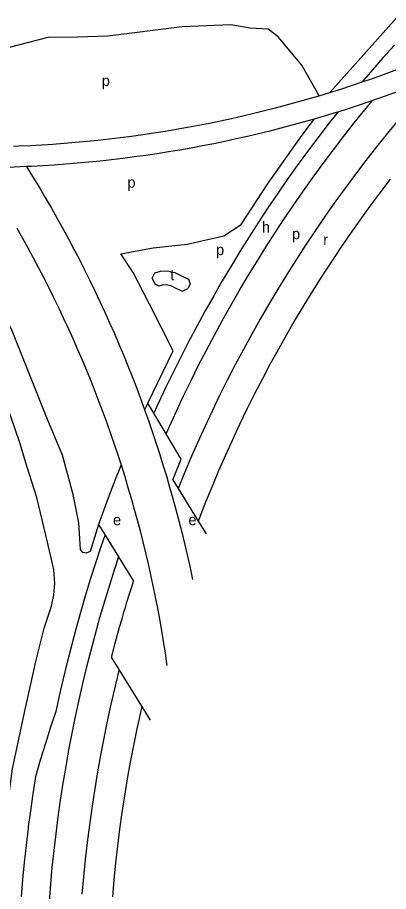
# Model space of a CAD drawing. Extents: x 155209 to 156755, y 386543 to 388502.
# Drawn here: x 156056.9 to 156193.5, y 387840.4 to 388161.9 of the extents above; entities that cross this region are included whole.
import ezdxf

# ---------------------------------------------------------------- set-up
doc = ezdxf.new("R2010")
doc.units = 0
doc.layers.add('BLT_Basislijn', color=7, linetype='Continuous')
doc.layers.add('BLT_Centroide', color=7, linetype='Continuous')

msp = doc.modelspace()

# ---------------------------------------------------------------- linework, layer by layer
at = {"layer": 'BLT_Basislijn'}
for points in [[(156196.55, 388161.95), (156184.36, 388148.27), (156171.92, 388134.38)], [(156167.94, 388133.17), (156161.61, 388144.38), (156152.92, 388154.87), (156149.22, 388157.64), (156142.57, 388158.01), (156135.46, 388159.23), (156117.57, 388158.48), (156090.11, 388155.04), (156078.96, 388154.76), (156068.1, 388154.57), (156049.4, 388149.84)], [(156195.68, 388151.8), (156191.47, 388147.07), (156183.81, 388138.24)], [(156183.81, 388138.24), (156187.58, 388139.54), (156191.43, 388140.9), (156191.64, 388140.98), (156195.55, 388142.41), (156197.63, 388143.19)], [(156171.92, 388134.38), (156175.89, 388135.63), (156179.85, 388136.91), (156183.81, 388138.24)], [(156210.82, 388140), (156210.06, 388139.69), (156206.14, 388138.15), (156202.2, 388136.63), (156198.24, 388135.14), (156194.27, 388133.69), (156194.05, 388133.61), (156190.14, 388132.22), (156187.58, 388131.34)], [(156167.94, 388133.17), (156171.92, 388134.38)], [(156055.39, 388114.62), (156057.47, 388114.69), (156061.63, 388114.88), (156065.78, 388115.11), (156069.93, 388115.37), (156074.08, 388115.68), (156078.22, 388116.02), (156082.37, 388116.4), (156086.5, 388116.82), (156090.64, 388117.27), (156094.77, 388117.77), (156098.89, 388118.3), (156103.01, 388118.88), (156107.13, 388119.49), (156111.23, 388120.13), (156115.34, 388120.82), (156119.43, 388121.54), (156123.52, 388122.31), (156127.6, 388123.11), (156131.68, 388123.94), (156135.74, 388124.82), (156139.8, 388125.73), (156143.85, 388126.68), (156147.89, 388127.67), (156151.92, 388128.7), (156155.94, 388129.76), (156159.95, 388130.86), (156163.95, 388131.99), (156167.94, 388133.17)], [(156111.62, 388008.74), (156112.82, 388011.45), (156115.41, 388017.13), (156118.07, 388022.78), (156120.79, 388028.4), (156123.59, 388033.98), (156126.45, 388039.53), (156129.37, 388045.05), (156132.36, 388050.53), (156135.42, 388055.98), (156138.54, 388061.38), (156141.73, 388066.75), (156144.98, 388072.09), (156148.29, 388077.38), (156151.67, 388082.63), (156155.11, 388087.84), (156158.61, 388093.02), (156162.17, 388098.14), (156165.79, 388103.23), (156169.48, 388108.27), (156173.22, 388113.27), (156177.03, 388118.22), (156180.89, 388123.13), (156184.81, 388127.99), (156187.58, 388131.34)], [(156187.58, 388131.34), (156186.21, 388130.87), (156182.27, 388129.55), (156178.25, 388128.24), (156174.85, 388127.17)], [(156166.11, 388124.55), (156162.04, 388123.39), (156157.96, 388122.27), (156153.87, 388121.19), (156149.77, 388120.15), (156145.66, 388119.15), (156141.54, 388118.18), (156137.41, 388117.25), (156133.27, 388116.36), (156129.13, 388115.51), (156124.98, 388114.69), (156120.82, 388113.92), (156116.65, 388113.18), (156112.48, 388112.48), (156108.3, 388111.83), (156104.11, 388111.2), (156099.92, 388110.62), (156095.73, 388110.08), (156091.52, 388109.58), (156087.32, 388109.11), (156083.11, 388108.68), (156078.9, 388108.3), (156074.68, 388107.95), (156070.46, 388107.64), (156066.24, 388107.37), (156062.01, 388107.14), (156060.21, 388107.06)], [(156094.94, 388075.02), (156106.85, 388077.23), (156119.31, 388078.54), (156132.91, 388081.66), (156139.3, 388085.76), (156148.97, 388100.67), (156160.7, 388117.35), (156166.11, 388124.55)], [(156174.85, 388127.17), (156171.3, 388122.67), (156167.45, 388117.65), (156163.65, 388112.58), (156159.91, 388107.47), (156156.24, 388102.32), (156152.63, 388097.12), (156149.08, 388091.87), (156145.59, 388086.59), (156142.17, 388081.26), (156138.81, 388075.9), (156135.51, 388070.49), (156132.28, 388065.05), (156129.12, 388059.56), (156126.02, 388054.04), (156122.99, 388048.48), (156120.02, 388042.89), (156117.12, 388037.26), (156114.29, 388031.6), (156111.53, 388025.9), (156108.83, 388020.17), (156107.08, 388016.33)], [(156174.85, 388127.17), (156174.21, 388126.97), (156170.17, 388125.74), (156166.11, 388124.55)], [(156197.17, 388124.26), (156193.11, 388119.33), (156189.12, 388114.35), (156185.19, 388109.32), (156181.33, 388104.25), (156177.52, 388099.12), (156173.79, 388093.95), (156170.11, 388088.73), (156166.5, 388083.47), (156162.96, 388078.16), (156159.49, 388072.81), (156156.08, 388067.42), (156152.74, 388061.98), (156149.47, 388056.5), (156146.27, 388050.98), (156143.13, 388045.43), (156140.07, 388039.83), (156137.08, 388034.2), (156134.15, 388028.52), (156131.3, 388022.82), (156128.52, 388017.07), (156125.81, 388011.3), (156123.18, 388005.49), (156120.61, 387999.64), (156118.12, 387993.77), (156116.01, 387988.61)], [(156060.21, 388107.06), (156057.79, 388106.95), (156053.56, 388106.79), (156049.33, 388106.68), (156045.1, 388106.61), (156043, 388106.59)], [(156060.21, 388107.06), (156062.82, 388102.83), (156065.05, 388099.15), (156067.24, 388095.46), (156069.4, 388091.74), (156071.52, 388088.01), (156073.61, 388084.26), (156075.66, 388080.48), (156077.68, 388076.69), (156079.66, 388072.88), (156081.61, 388069.05), (156083.52, 388065.2), (156085.4, 388061.34), (156087.24, 388057.46), (156089.04, 388053.56), (156090.81, 388049.64), (156092.54, 388045.71), (156094.24, 388041.77), (156095.9, 388037.8), (156097.52, 388033.83), (156099.11, 388029.83), (156100.65, 388025.83), (156102.17, 388021.8), (156103.64, 388017.77), (156103.7, 388017.6)], [(156194.1, 388102.45), (156190.32, 388097.49), (156186.6, 388092.48), (156182.94, 388087.42), (156179.35, 388082.32), (156175.82, 388077.17), (156172.36, 388071.98), (156168.96, 388066.74), (156165.63, 388061.47), (156162.36, 388056.15), (156159.16, 388050.8), (156156.03, 388045.4), (156152.97, 388039.96), (156149.97, 388034.49), (156147.04, 388028.98), (156144.18, 388023.43), (156141.39, 388017.85), (156138.68, 388012.23), (156136.03, 388006.58), (156133.45, 388000.9), (156130.94, 387995.19), (156128.51, 387989.44), (156126.14, 387983.67), (156123.85, 387977.86), (156123.4, 387976.67)], [(156056.61, 388084.4), (156058.66, 388080.78), (156060.69, 388077.15), (156062.67, 388073.49), (156064.63, 388069.82), (156066.55, 388066.13), (156068.43, 388062.42), (156070.28, 388058.7), (156072.1, 388054.96), (156073.88, 388051.2), (156075.63, 388047.42), (156077.34, 388043.63), (156079.02, 388039.83), (156080.66, 388036.01), (156082.27, 388032.17), (156083.84, 388028.32), (156085.37, 388024.45), (156086.87, 388020.57), (156088.33, 388016.68), (156089.76, 388012.77), (156091.15, 388008.85), (156092.51, 388004.92), (156093.82, 388000.98), (156095.02, 387997.3)], [(156104.83, 388020.08), (156114.23, 388039.31), (156105.52, 388056.47), (156099.44, 388068.09), (156094.94, 388075.02)], [(156086.71, 387975.42), (156083.62, 387965.53), (156082.18, 387964.88), (156080.95, 387965.05), (156080.09, 387966.17), (156079.98, 387968.26), (156079.45, 387976.02), (156077.32, 387986.39), (156073.39, 388000.91), (156067.67, 388014.68), (156054.66, 388047.27), (156045.97, 388063.2), (156043.35, 388067.79), (156040.88, 388069.21)], [(156106.49, 388065.99), (156107.42, 388067.97), (156109.49, 388068.57), (156112.01, 388068.69), (156114.83, 388068.06), (156117.48, 388066.78), (156119.88, 388065.71), (156120.46, 388063.78), (156119.64, 388062.21)], [(156106.49, 388065.99), (156107.44, 388063.91), (156108.94, 388063.19), (156109.07, 388063.24), (156110.32, 388063.61), (156111.58, 388063.67), (156113.17, 388063.31), (156115.38, 388062.24), (156117.6, 388061.26), (156119.64, 388062.21)], [(156050.07, 387847.39), (156050.9, 387853.97), (156053.11, 387870.76), (156055.02, 387885.54), (156059.43, 387906.19), (156063.59, 387925.01), (156066.66, 387937.3), (156069.34, 387945.34), (156070.21, 387949.52), (156070.6, 387953.7), (156070.21, 387958.82), (156067.9, 387968.89), (156064.04, 387985.37), (156060.48, 387996.56), (156057.72, 388005.47), (156054.41, 388015.09), (156051.65, 388023.05), (156050, 388027.22)], [(156104.83, 388020.08), (156103.7, 388017.6)], [(156107.08, 388016.33), (156104.83, 388020.08)], [(156103.7, 388017.6), (156105.08, 388013.72), (156106.47, 388009.66), (156107.84, 388005.58), (156109.16, 388001.5), (156110.44, 387997.4), (156111.69, 387993.29), (156112.9, 387989.17), (156114.07, 387985.03), (156115.2, 387980.89), (156116.3, 387976.73), (156117.35, 387972.57), (156118.37, 387968.4), (156119.35, 387964.21), (156120.29, 387960.02), (156121.19, 387955.82), (156121.33, 387955.16)], [(156111.62, 388008.74), (156107.08, 388016.33)], [(156117.2, 387999.42), (156111.62, 388008.74)], [(156114.03, 387991.82), (156117.2, 387999.42)], [(156095.02, 387997.3), (156093.78, 387994.26), (156093.36, 387993.19), (156090.14, 387984.81), (156086.71, 387975.42)], [(156095.02, 387997.3), (156096.35, 387993.05), (156097.56, 387989.07), (156098.73, 387985.08), (156099.86, 387981.08), (156100.96, 387977.07), (156102.02, 387973.04), (156103.04, 387969.01), (156104.03, 387964.97), (156104.97, 387960.92), (156105.88, 387956.86), (156106.76, 387952.8), (156107.59, 387948.72), (156108.39, 387944.64), (156109.15, 387940.55), (156109.87, 387936.45), (156110.14, 387934.86), (156110.55, 387932.35), (156111.2, 387928.24), (156111.8, 387924.13), (156111.88, 387923.57)], [(156114.03, 387991.82), (156116.01, 387988.61)], [(156116.01, 387988.61), (156123.4, 387976.67)], [(156123.4, 387976.67), (156126.34, 387971.92)], [(156086.71, 387975.42), (156089.15, 387971.48)], [(156058.34, 387838.39), (156058.87, 387844.74), (156059.47, 387851.08), (156060.15, 387857.41), (156060.9, 387863.73), (156060.97, 387864.27), (156061.73, 387870.04), (156062.63, 387876.35), (156063.61, 387882.64), (156065.4, 387888.79), (156067.27, 387894.91), (156069.21, 387901), (156071.21, 387907.05), (156071.22, 387907.08), (156072.38, 387912.43), (156073.79, 387918.6), (156075.27, 387924.76), (156076.83, 387930.89), (156078.46, 387937.01), (156080.16, 387943.11), (156081.94, 387949.19), (156083.79, 387955.24), (156085.71, 387961.27), (156087.7, 387967.28), (156089.15, 387971.48)], [(156089.15, 387971.48), (156094.09, 387963.5)], [(156094.09, 387963.5), (156092.61, 387959.03), (156090.71, 387953.08), (156088.89, 387947.11), (156087.13, 387941.12), (156085.45, 387935.1), (156083.85, 387929.07), (156082.31, 387923.02), (156080.85, 387916.94), (156079.46, 387910.86), (156078.14, 387904.75), (156076.89, 387898.63), (156075.72, 387892.5), (156074.62, 387886.35), (156073.6, 387880.19), (156072.65, 387874.02), (156071.77, 387867.84), (156070.97, 387861.65), (156070.24, 387855.44), (156069.58, 387849.23), (156069.45, 387847.82), (156069, 387843.02), (156068.5, 387836.79)], [(156094.09, 387963.5), (156099.61, 387954.57)], [(156094.33, 387922.08), (156091.51, 387926.63), (156091.95, 387928.31), (156092.78, 387931.41), (156093.24, 387933.11), (156093.72, 387934.88), (156094.49, 387937.61), (156095.37, 387940.7), (156096.08, 387943.11), (156096.6, 387944.83), (156097.2, 387946.86), (156098.15, 387949.94), (156099.18, 387953.23), (156099.61, 387954.57)], [(156094.33, 387922.08), (156094.09, 387921.15), (156092.58, 387914.95), (156091.15, 387908.73), (156089.8, 387902.49), (156088.52, 387896.24), (156087.33, 387889.97), (156086.21, 387883.69), (156085.18, 387877.39), (156084.22, 387871.09), (156083.34, 387864.77), (156082.54, 387858.44), (156081.81, 387852.1), (156081.17, 387845.75), (156080.61, 387839.39)], [(156102.66, 387908.61), (156094.33, 387922.08)], [(156102.66, 387908.61), (156102.13, 387906.28), (156100.81, 387900.18), (156099.56, 387894.06), (156098.39, 387887.93), (156097.3, 387881.79), (156096.29, 387875.63), (156095.35, 387869.46), (156094.49, 387863.28), (156093.7, 387857.09), (156093, 387850.89), (156092.37, 387844.69), (156091.82, 387838.47)], [(156105.86, 387903.44), (156102.66, 387908.61)]]:
    msp.add_lwpolyline(points, dxfattribs=at)

# ---------------------------------------------------------------- texts
at = {"layer": 'BLT_Centroide'}
for s, p in [('p', (156087.92, 388136.71)), ('p', (156097.37, 388099.31)), ('h', (156146.89, 388082.81)), ('p', (156157.96, 388080.37)), ('r', (156169.45, 388078.2)), ('p', (156130.01, 388074.51)), ('t', (156113.15, 388065.26)), ('e', (156092.06, 387975.13)), ('e', (156119.82, 387975.13))]:
    msp.add_text(s, height=4, dxfattribs=at).set_placement(p)

doc.saveas('drawing.dxf')
